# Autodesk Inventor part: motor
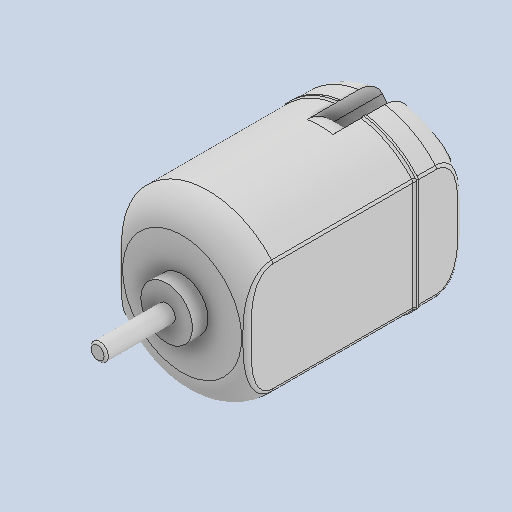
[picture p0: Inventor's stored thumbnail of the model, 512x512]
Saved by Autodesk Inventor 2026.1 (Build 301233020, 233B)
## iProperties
Created: 2019-04
Part Number: motor
Material: Generic
Document SubType Name: Modeling
Designer: hp
Density: 1 g/cm^3
Appearance: Default
Author: hp
Revision Number: ANY
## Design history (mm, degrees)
fillet "Fillet6"
body "Solid1"
